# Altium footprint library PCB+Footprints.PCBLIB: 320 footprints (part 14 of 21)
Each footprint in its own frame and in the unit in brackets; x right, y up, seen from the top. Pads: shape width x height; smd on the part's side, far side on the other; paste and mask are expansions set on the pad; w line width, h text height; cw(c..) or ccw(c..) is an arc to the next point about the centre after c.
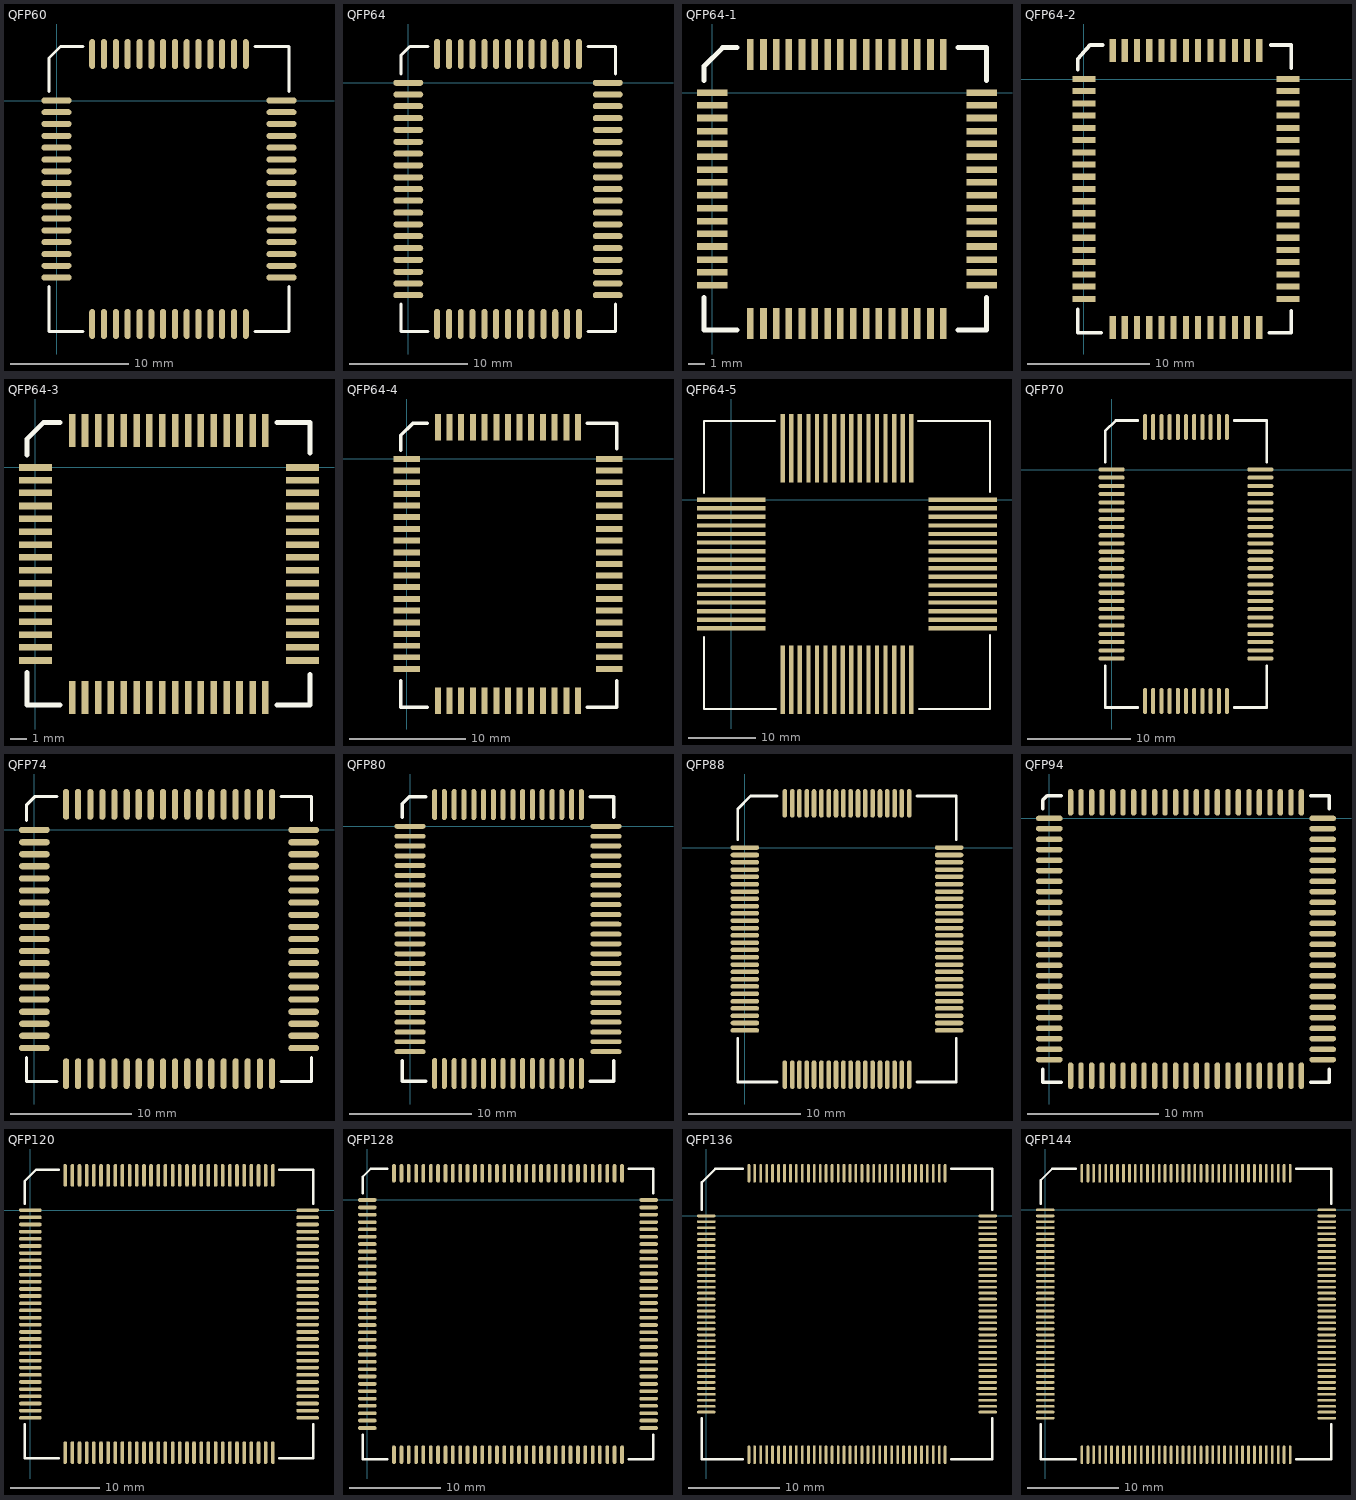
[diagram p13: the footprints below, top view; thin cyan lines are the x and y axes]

## QFP60 [mil]
pads (60):
  oval 100x20 smd: 1(0,0) 2(0,-39) 3(0,-78) 4(0,-118) 5(0,-157) 6(0,-197) 7(0,-236) 8(0,-275) 9(0,-315) 10(0,-354) 11(0,-393) 12(0,-433) 13(0,-472) 14(0,-512) 15(0,-551) 16(0,-590) 31(750,-590) 32(750,-551) 33(750,-512) 34(750,-472) 35(750,-433) 36(750,-393) 37(750,-354) 38(750,-315) 39(750,-275) 40(750,-236) 41(750,-197) 42(750,-157) 43(750,-118) 44(750,-78) 45(750,-39) 46(750,0)
  oval 20x100 smd: 17(119,-745) 18(158,-745) 19(198,-745) 20(237,-745) 21(277,-745) 22(316,-745) 23(355,-745) 24(395,-745) 25(434,-745) 26(473,-745) 27(513,-745) 28(552,-745) 29(592,-745) 30(631,-745) 47(631,155) 48(592,155) 49(552,155) 50(513,155) 51(473,155) 52(434,155) 53(395,155) 54(355,155) 55(316,155) 56(277,155) 57(237,155) 58(198,155) 59(158,155) 60(119,155)
TopOverlay:
  lines w10: -25,-620 -25,-770 89,-770 ; -25,30 -25,142 13,180 89,180 ; 661,-770 775,-770 775,-620 ; 661,180 775,180 775,30

## QFP64 [mil]
pads (64):
  oval 100x20 smd: 1(0,0) 2(0,-39) 3(0,-78) 4(0,-118) 5(0,-157) 6(0,-197) 7(0,-236) 8(0,-275) 9(0,-315) 10(0,-354) 11(0,-393) 12(0,-433) 13(0,-472) 14(0,-511) 15(0,-551) 16(0,-590) 17(0,-630) 18(0,-669) 19(0,-708) 33(665,-708) 34(665,-669) 35(665,-630) 36(665,-590) 37(665,-551) 38(665,-511) 39(665,-472) 40(665,-433) 41(665,-393) 42(665,-354) 43(665,-315) 44(665,-275) 45(665,-236) 46(665,-197) 47(665,-157) 48(665,-118) 49(665,-78) 50(665,-39) 51(665,0)
  oval 20x100 smd: 20(96,-804) 21(136,-804) 22(175,-804) 23(214,-804) 24(254,-804) 25(293,-804) 26(333,-804) 27(372,-804) 28(411,-804) 29(451,-804) 30(490,-804) 31(529,-804) 32(569,-804) 52(569,96) 53(529,96) 54(490,96) 55(451,96) 56(411,96) 57(372,96) 58(333,96) 59(293,96) 60(254,96) 61(214,96) 62(175,96) 63(136,96) 64(96,96)
TopOverlay:
  lines w10: -25,-738 -25,-829 66,-829 ; -25,30 -25,91 5,121 66,121 ; 599,-829 690,-829 690,-738 ; 599,121 690,121 690,30

## QFP64-1 [mil]
pads (64):
  rect 75x16 smd: 1(0,0) 2(0,-31) 3(0,-62) 4(0,-94) 5(0,-125) 6(0,-157) 7(0,-188) 8(0,-219) 9(0,-251) 10(0,-282) 11(0,-314) 12(0,-345) 13(0,-376) 14(0,-408) 15(0,-439) 16(0,-471) 33(658,-471) 34(658,-439) 35(658,-408) 36(658,-376) 37(658,-345) 38(658,-314) 39(658,-282) 40(658,-251) 41(658,-219) 42(658,-188) 43(658,-157) 44(658,-125) 45(658,-94) 46(658,-62) 47(658,-31) 48(658,0)
  rect 16x75 smd: 17(93,-564) 18(125,-564) 19(156,-564) 20(187,-564) 21(219,-564) 22(250,-564) 23(282,-564) 24(313,-564) 25(344,-564) 26(376,-564) 27(407,-564) 28(439,-564) 29(470,-564) 30(501,-564) 31(533,-564) 32(564,-564) 49(564,93) 50(533,93) 51(501,93) 52(470,93) 53(439,93) 54(407,93) 55(376,93) 56(344,93) 57(313,93) 58(282,93) 59(250,93) 60(219,93) 61(187,93) 62(156,93) 63(125,93) 64(93,93)
TopOverlay:
  lines w12: -20,-500 -20,-580 60,-580 ; -20,30 -20,65 25,110 60,110 ; 600,-580 670,-580 670,-500 ; 600,110 670,110 670,30

## QFP64-2 [mil]
pads (64):
  rect 75x20 smd: 1(0,0) 2(0,-39) 3(0,-79) 4(0,-118) 5(0,-158) 6(0,-197) 7(0,-237) 8(0,-276) 9(0,-316) 10(0,-355) 11(0,-395) 12(0,-434) 13(0,-474) 14(0,-513) 15(0,-553) 16(0,-592) 17(0,-632) 18(0,-671) 19(0,-711) 33(660,-711) 34(660,-671) 35(660,-632) 36(660,-592) 37(660,-553) 38(660,-513) 39(660,-474) 40(660,-434) 41(660,-395) 42(660,-355) 43(660,-316) 44(660,-276) 45(660,-237) 46(660,-197) 47(660,-158) 48(660,-118) 49(660,-79) 50(660,-39) 51(660,0)
  rect 20x75 smd: 20(93,-803) 21(132,-803) 22(172,-803) 23(211,-803) 24(251,-803) 25(290,-803) 26(330,-803) 27(369,-803) 28(409,-803) 29(448,-803) 30(488,-803) 31(527,-803) 32(567,-803) 52(567,92) 53(527,92) 54(488,92) 55(448,92) 56(409,92) 57(369,92) 58(330,92) 59(290,92) 60(251,92) 61(211,92) 62(172,92) 63(132,92) 64(93,92)
TopOverlay:
  lines w12: -20,-745 -20,-820 55,-820 ; -20,30 -20,65 20,110 60,110 ; 600,-820 670,-820 670,-750 ; 605,110 670,110 670,35

## QFP64-3 [mil]
pads (64):
  rect 80x16 smd: 1(0,0) 2(0,-31) 3(0,-62) 4(0,-94) 5(0,-125) 6(0,-157) 7(0,-188) 8(0,-219) 9(0,-251) 10(0,-282) 11(0,-314) 12(0,-345) 13(0,-376) 14(0,-408) 15(0,-439) 16(0,-471) 33(652,-471) 34(652,-439) 35(652,-408) 36(652,-376) 37(652,-345) 38(652,-314) 39(652,-282) 40(652,-251) 41(652,-219) 42(652,-188) 43(652,-157) 44(652,-125) 45(652,-94) 46(652,-62) 47(652,-31) 48(652,0)
  rect 16x80 smd: 17(90,-561) 18(121,-561) 19(153,-561) 20(184,-561) 21(216,-561) 22(247,-561) 23(278,-561) 24(310,-561) 25(341,-561) 26(373,-561) 27(404,-561) 28(435,-561) 29(467,-561) 30(498,-561) 31(530,-561) 32(561,-561) 49(561,90) 50(530,90) 51(498,90) 52(467,90) 53(435,90) 54(404,90) 55(373,90) 56(341,90) 57(310,90) 58(278,90) 59(247,90) 60(216,90) 61(184,90) 62(153,90) 63(121,90) 64(90,90)
TopOverlay:
  lines w12: -20,-500 -20,-580 60,-580 ; -20,30 -20,70 20,110 60,110 ; 590,-580 670,-580 670,-505 ; 590,110 670,110 670,35

## QFP64-4 [mil]
pads (64):
  rect 90x20 smd: 1(0,0) 2(0,-39) 3(0,-79) 4(0,-118) 5(0,-158) 6(0,-197) 7(0,-237) 8(0,-276) 9(0,-316) 10(0,-355) 11(0,-395) 12(0,-434) 13(0,-474) 14(0,-513) 15(0,-553) 16(0,-592) 17(0,-632) 18(0,-671) 19(0,-711) 33(685,-711) 34(685,-671) 35(685,-632) 36(685,-592) 37(685,-553) 38(685,-513) 39(685,-474) 40(685,-434) 41(685,-395) 42(685,-355) 43(685,-316) 44(685,-276) 45(685,-237) 46(685,-197) 47(685,-158) 48(685,-118) 49(685,-79) 50(685,-39) 51(685,0)
  rect 20x90 smd: 20(105,-818) 21(145,-818) 22(184,-818) 23(224,-818) 24(263,-818) 25(303,-818) 26(342,-818) 27(382,-818) 28(421,-818) 29(461,-818) 30(500,-818) 31(540,-818) 32(579,-818) 52(579,107) 53(540,107) 54(500,107) 55(461,107) 56(421,107) 57(382,107) 58(342,107) 59(303,107) 60(263,107) 61(224,107) 62(184,107) 63(145,107) 64(105,107)
TopOverlay:
  lines w12: -20,-750 -20,-840 70,-840 ; -20,30 -20,80 20,120 70,120 ; 610,-840 710,-840 710,-750 ; 610,120 710,120 710,35

## QFP64-5 [mil]
pads (64):
  rect 400x25 smd: 1(0,0) 2(0,-50) 3(0,-100) 4(0,-150) 5(0,-200) 6(0,-250) 7(0,-300) 8(0,-350) 9(0,-400) 10(0,-450) 11(0,-500) 12(0,-550) 13(0,-600) 14(0,-650) 15(0,-700) 16(0,-750) 33(1350,-750) 34(1350,-700) 35(1350,-650) 36(1350,-600) 37(1350,-550) 38(1350,-500) 39(1350,-450) 40(1350,-400) 41(1350,-350) 42(1350,-300) 43(1350,-250) 44(1350,-200) 45(1350,-150) 46(1350,-100) 47(1350,-50) 48(1350,0)
  rect 25x400 smd: 17(300,-1050) 18(350,-1050) 19(400,-1050) 20(450,-1050) 21(500,-1050) 22(550,-1050) 23(600,-1050) 24(650,-1050) 25(700,-1050) 26(750,-1050) 27(800,-1050) 28(850,-1050) 29(900,-1050) 30(950,-1050) 31(1000,-1050) 32(1050,-1050) 49(1050,300) 50(1000,300) 51(950,300) 52(900,300) 53(850,300) 54(800,300) 55(750,300) 56(700,300) 57(650,300) 58(600,300) 59(550,300) 60(500,300) 61(450,300) 62(400,300) 63(350,300) 64(300,300)
TopOverlay:
  lines w12: -160,-800 -160,-1220 260,-1220 ; -160,40 -160,460 255,460 ; 1090,460 1510,460 1510,45 ; 1095,-1220 1510,-1220 1510,-790

## QFP70 [mil]
pads (70):
  oval 100x16 smd: 1(0,0) 2(0,-31) 3(0,-63) 4(0,-94) 5(0,-126) 6(0,-157) 7(0,-189) 8(0,-220) 9(0,-252) 10(0,-283) 11(0,-315) 12(0,-346) 13(0,-378) 14(0,-409) 15(0,-441) 16(0,-472) 17(0,-504) 18(0,-535) 19(0,-567) 20(0,-598) 21(0,-630) 22(0,-661) 23(0,-693) 24(0,-724) 36(570,-724) 37(570,-693) 38(570,-661) 39(570,-630) 40(570,-598) 41(570,-567) 42(570,-535) 43(570,-504) 44(570,-472) 45(570,-441) 46(570,-409) 47(570,-378) 48(570,-346) 49(570,-315) 50(570,-283) 51(570,-252) 52(570,-220) 53(570,-189) 54(570,-157) 55(570,-126) 56(570,-94) 57(570,-63) 58(570,-31) 59(570,0)
  oval 16x100 smd: 25(128,-887) 26(159,-887) 27(191,-887) 28(222,-887) 29(254,-887) 30(285,-887) 31(316,-887) 32(348,-887) 33(379,-887) 34(411,-887) 35(442,-887) 60(442,163) 61(411,163) 62(379,163) 63(348,163) 64(316,163) 65(285,163) 66(254,163) 67(222,163) 68(191,163) 69(159,163) 70(128,163)
TopOverlay:
  lines w10: -25,-752 -25,-912 100,-912 ; -25,28 -25,147 16,188 100,188 ; 470,-912 595,-912 595,-752 ; 470,188 595,188 595,28

## QFP74 [mil]
pads (74):
  oval 100x20 smd: 1(0,0) 2(0,-40) 3(0,-79) 4(0,-118) 5(0,-158) 6(0,-197) 7(0,-236) 8(0,-276) 9(0,-315) 10(0,-355) 11(0,-394) 12(0,-433) 13(0,-473) 14(0,-512) 15(0,-551) 16(0,-591) 17(0,-630) 18(0,-669) 19(0,-709) 38(875,-709) 39(875,-669) 40(875,-630) 41(875,-591) 42(875,-551) 43(875,-512) 44(875,-473) 45(875,-433) 46(875,-394) 47(875,-355) 48(875,-315) 49(875,-276) 50(875,-236) 51(875,-197) 52(875,-158) 53(875,-118) 54(875,-79) 55(875,-40) 56(875,0)
  oval 20x100 smd: 20(103,-792) 21(142,-792) 22(182,-792) 23(221,-792) 24(260,-792) 25(300,-792) 26(339,-792) 27(378,-792) 28(418,-792) 29(457,-792) 30(497,-792) 31(536,-792) 32(575,-792) 33(615,-792) 34(654,-792) 35(693,-792) 36(733,-792) 37(772,-792) 57(772,83) 58(733,83) 59(693,83) 60(654,83) 61(615,83) 62(575,83) 63(536,83) 64(497,83) 65(457,83) 66(418,83) 67(378,83) 68(339,83) 69(300,83) 70(260,83) 71(221,83) 72(182,83) 73(142,83) 74(103,83)
TopOverlay:
  lines w10: -25,-739 -25,-817 73,-817 ; -25,30 -25,82 1,108 73,108 ; 802,-817 900,-817 900,-739 ; 802,108 900,108 900,30

## QFP80 [mil]
pads (80):
  oval 100x16 smd: 1(0,0) 2(0,-32) 3(0,-63) 4(0,-95) 5(0,-126) 6(0,-158) 7(0,-189) 8(0,-221) 9(0,-252) 10(0,-284) 11(0,-315) 12(0,-347) 13(0,-378) 14(0,-410) 15(0,-441) 16(0,-473) 17(0,-504) 18(0,-536) 19(0,-567) 20(0,-599) 21(0,-630) 22(0,-662) 23(0,-693) 24(0,-725) 41(630,-725) 42(630,-693) 43(630,-662) 44(630,-630) 45(630,-599) 46(630,-567) 47(630,-536) 48(630,-504) 49(630,-473) 50(630,-441) 51(630,-410) 52(630,-378) 53(630,-347) 54(630,-315) 55(630,-284) 56(630,-252) 57(630,-221) 58(630,-189) 59(630,-158) 60(630,-126) 61(630,-95) 62(630,-63) 63(630,-32) 64(630,0)
  oval 16x100 smd: 25(79,-795) 26(110,-795) 27(142,-795) 28(173,-795) 29(205,-795) 30(236,-795) 31(268,-795) 32(299,-795) 33(331,-795) 34(362,-795) 35(394,-795) 36(425,-795) 37(457,-795) 38(488,-795) 39(520,-795) 40(551,-795) 65(551,70) 66(520,70) 67(488,70) 68(457,70) 69(425,70) 70(394,70) 71(362,70) 72(331,70) 73(299,70) 74(268,70) 75(236,70) 76(205,70) 77(173,70) 78(142,70) 79(110,70) 80(79,70)
TopOverlay:
  lines w10: -25,-753 -25,-820 51,-820 ; -25,28 -25,73 -3,95 51,95 ; 579,-820 655,-820 655,-753 ; 579,95 655,95 655,28

## QFP88 [mil]
pads (88):
  oval 100x16 smd: 1(0,0) 2(0,-26) 3(0,-51) 4(0,-77) 5(0,-102) 6(0,-128) 7(0,-154) 8(0,-179) 9(0,-205) 10(0,-230) 11(0,-256) 12(0,-282) 13(0,-307) 14(0,-333) 15(0,-358) 16(0,-384) 17(0,-410) 18(0,-435) 19(0,-461) 20(0,-486) 21(0,-512) 22(0,-538) 23(0,-563) 24(0,-589) 25(0,-614) 26(0,-640) 45(715,-640) 46(715,-614) 47(715,-589) 48(715,-563) 49(715,-538) 50(715,-512) 51(715,-486) 52(715,-461) 53(715,-435) 54(715,-410) 55(715,-384) 56(715,-358) 57(715,-333) 58(715,-307) 59(715,-282) 60(715,-256) 61(715,-230) 62(715,-205) 63(715,-179) 64(715,-154) 65(715,-128) 66(715,-102) 67(715,-77) 68(715,-51) 69(715,-26) 70(715,0)
  oval 16x100 smd: 27(140,-795) 28(166,-795) 29(191,-795) 30(217,-795) 31(242,-795) 32(268,-795) 33(294,-795) 34(319,-795) 35(345,-795) 36(370,-795) 37(396,-795) 38(421,-795) 39(447,-795) 40(473,-795) 41(498,-795) 42(524,-795) 43(549,-795) 44(575,-795) 71(575,155) 72(549,155) 73(524,155) 74(498,155) 75(473,155) 76(447,155) 77(421,155) 78(396,155) 79(370,155) 80(345,155) 81(319,155) 82(294,155) 83(268,155) 84(242,155) 85(217,155) 86(191,155) 87(166,155) 88(140,155)
TopOverlay:
  lines w10: -25,-668 -25,-820 112,-820 ; -25,28 -25,135 20,180 112,180 ; 603,-820 740,-820 740,-668 ; 603,180 740,180 740,28

## QFP94 [mil]
pads (94):
  oval 80x16 smd: 1(0,0) 2(0,-31) 3(0,-63) 4(0,-94) 5(0,-126) 6(0,-157) 7(0,-189) 8(0,-220) 9(0,-252) 10(0,-283) 11(0,-315) 12(0,-346) 13(0,-378) 14(0,-409) 15(0,-441) 16(0,-472) 17(0,-504) 18(0,-535) 19(0,-567) 20(0,-598) 21(0,-630) 22(0,-661) 23(0,-693) 24(0,-724) 48(820,-724) 49(820,-693) 50(820,-661) 51(820,-630) 52(820,-598) 53(820,-567) 54(820,-535) 55(820,-504) 56(820,-472) 57(820,-441) 58(820,-409) 59(820,-378) 60(820,-346) 61(820,-315) 62(820,-283) 63(820,-252) 64(820,-220) 65(820,-189) 66(820,-157) 67(820,-126) 68(820,-94) 69(820,-63) 70(820,-31) 71(820,0)
  oval 16x80 smd: 25(64,-772) 26(95,-772) 27(127,-772) 28(158,-772) 29(190,-772) 30(221,-772) 31(253,-772) 32(284,-772) 33(316,-772) 34(347,-772) 35(379,-772) 36(410,-772) 37(441,-772) 38(473,-772) 39(504,-772) 40(536,-772) 41(567,-772) 42(599,-772) 43(630,-772) 44(662,-772) 45(693,-772) 46(725,-772) 47(756,-772) 72(756,48) 73(725,48) 74(693,48) 75(662,48) 76(630,48) 77(599,48) 78(567,48) 79(536,48) 80(504,48) 81(473,48) 82(441,48) 83(410,48) 84(379,48) 85(347,48) 86(316,48) 87(284,48) 88(253,48) 89(221,48) 90(190,48) 91(158,48) 92(127,48) 93(95,48) 94(64,48)
TopOverlay:
  lines w10: -20,-752 -20,-792 36,-792 ; -20,28 -20,55 -7,68 36,68 ; 784,-792 840,-792 840,-752 ; 784,68 840,68 840,28

## QFP120 [mil]
pads (120):
  oval 100x16 smd: 1(0,0) 2(0,-32) 3(0,-63) 4(0,-95) 5(0,-126) 6(0,-158) 7(0,-189) 8(0,-221) 9(0,-252) 10(0,-284) 11(0,-315) 12(0,-347) 13(0,-378) 14(0,-410) 15(0,-441) 16(0,-473) 17(0,-504) 18(0,-536) 19(0,-567) 20(0,-599) 21(0,-630) 22(0,-662) 23(0,-693) 24(0,-725) 25(0,-756) 26(0,-788) 27(0,-819) 28(0,-851) 29(0,-882) 30(0,-914) 61(1220,-914) 62(1220,-882) 63(1220,-851) 64(1220,-819) 65(1220,-788) 66(1220,-756) 67(1220,-725) 68(1220,-693) 69(1220,-662) 70(1220,-630) 71(1220,-599) 72(1220,-567) 73(1220,-536) 74(1220,-504) 75(1220,-473) 76(1220,-441) 77(1220,-410) 78(1220,-378) 79(1220,-347) 80(1220,-315) 81(1220,-284) 82(1220,-252) 83(1220,-221) 84(1220,-189) 85(1220,-158) 86(1220,-126) 87(1220,-95) 88(1220,-63) 89(1220,-32) 90(1220,0)
  oval 16x100 smd: 31(153,-1067) 32(185,-1067) 33(216,-1067) 34(248,-1067) 35(279,-1067) 36(311,-1067) 37(342,-1067) 38(374,-1067) 39(405,-1067) 40(437,-1067) 41(468,-1067) 42(500,-1067) 43(531,-1067) 44(563,-1067) 45(594,-1067) 46(626,-1067) 47(657,-1067) 48(689,-1067) 49(720,-1067) 50(752,-1067) 51(783,-1067) 52(815,-1067) 53(846,-1067) 54(878,-1067) 55(909,-1067) 56(941,-1067) 57(972,-1067) 58(1004,-1067) 59(1035,-1067) 60(1067,-1067) 91(1067,153) 92(1035,153) 93(1004,153) 94(972,153) 95(941,153) 96(909,153) 97(878,153) 98(846,153) 99(815,153) 100(783,153) 101(752,153) 102(720,153) 103(689,153) 104(657,153) 105(626,153) 106(594,153) 107(563,153) 108(531,153) 109(500,153) 110(468,153) 111(437,153) 112(405,153) 113(374,153) 114(342,153) 115(311,153) 116(279,153) 117(248,153) 118(216,153) 119(185,153) 120(153,153)
TopOverlay:
  lines w10: -25,-942 -25,-1092 125,-1092 ; -25,28 -25,128 25,178 125,178 ; 1095,-1092 1245,-1092 1245,-942 ; 1095,178 1245,178 1245,28

## QFP128 [mil]
pads (128):
  oval 80x16 smd: 1(0,0) 2(0,-32) 3(0,-63) 4(0,-95) 5(0,-126) 6(0,-158) 7(0,-189) 8(0,-221) 9(0,-252) 10(0,-284) 11(0,-315) 12(0,-347) 13(0,-378) 14(0,-410) 15(0,-441) 16(0,-473) 17(0,-504) 18(0,-536) 19(0,-567) 20(0,-599) 21(0,-630) 22(0,-662) 23(0,-693) 24(0,-725) 25(0,-756) 26(0,-788) 27(0,-819) 28(0,-851) 29(0,-882) 30(0,-914) 31(0,-945) 32(0,-977) 65(1205,-977) 66(1205,-945) 67(1205,-914) 68(1205,-882) 69(1205,-851) 70(1205,-819) 71(1205,-788) 72(1205,-756) 73(1205,-725) 74(1205,-693) 75(1205,-662) 76(1205,-630) 77(1205,-599) 78(1205,-567) 79(1205,-536) 80(1205,-504) 81(1205,-473) 82(1205,-441) 83(1205,-410) 84(1205,-378) 85(1205,-347) 86(1205,-315) 87(1205,-284) 88(1205,-252) 89(1205,-221) 90(1205,-189) 91(1205,-158) 92(1205,-126) 93(1205,-95) 94(1205,-63) 95(1205,-32) 96(1205,0)
  oval 16x80 smd: 33(114,-1091) 34(146,-1091) 35(177,-1091) 36(209,-1091) 37(240,-1091) 38(272,-1091) 39(303,-1091) 40(335,-1091) 41(366,-1091) 42(398,-1091) 43(429,-1091) 44(461,-1091) 45(492,-1091) 46(524,-1091) 47(555,-1091) 48(587,-1091) 49(618,-1091) 50(650,-1091) 51(681,-1091) 52(713,-1091) 53(744,-1091) 54(776,-1091) 55(807,-1091) 56(839,-1091) 57(870,-1091) 58(902,-1091) 59(933,-1091) 60(965,-1091) 61(996,-1091) 62(1028,-1091) 63(1059,-1091) 64(1091,-1091) 97(1091,114) 98(1059,114) 99(1028,114) 100(996,114) 101(965,114) 102(933,114) 103(902,114) 104(870,114) 105(839,114) 106(807,114) 107(776,114) 108(744,114) 109(713,114) 110(681,114) 111(650,114) 112(618,114) 113(587,114) 114(555,114) 115(524,114) 116(492,114) 117(461,114) 118(429,114) 119(398,114) 120(366,114) 121(335,114) 122(303,114) 123(272,114) 124(240,114) 125(209,114) 126(177,114) 127(146,114) 128(114,114)
TopOverlay:
  lines w10: -20,-1005 -20,-1111 86,-1111 ; -20,28 -20,99 15,134 86,134 ; 1119,-1111 1225,-1111 1225,-1005 ; 1119,134 1225,134 1225,28

## QFP136 [mil]
pads (136):
  oval 80x12 smd: 1(0,0) 2(0,-25) 3(0,-51) 4(0,-77) 5(0,-102) 6(0,-128) 7(0,-153) 8(0,-179) 9(0,-204) 10(0,-230) 11(0,-256) 12(0,-281) 13(0,-307) 14(0,-332) 15(0,-358) 16(0,-384) 17(0,-409) 18(0,-435) 19(0,-460) 20(0,-486) 21(0,-512) 22(0,-537) 23(0,-563) 24(0,-588) 25(0,-614) 26(0,-640) 27(0,-665) 28(0,-691) 29(0,-716) 30(0,-742) 31(0,-767) 32(0,-793) 33(0,-819) 34(0,-844) 69(1210,-844) 70(1210,-819) 71(1210,-793) 72(1210,-767) 73(1210,-742) 74(1210,-716) 75(1210,-691) 76(1210,-665) 77(1210,-640) 78(1210,-614) 79(1210,-588) 80(1210,-563) 81(1210,-537) 82(1210,-512) 83(1210,-486) 84(1210,-460) 85(1210,-435) 86(1210,-409) 87(1210,-384) 88(1210,-358) 89(1210,-332) 90(1210,-307) 91(1210,-281) 92(1210,-256) 93(1210,-230) 94(1210,-204) 95(1210,-179) 96(1210,-153) 97(1210,-128) 98(1210,-102) 99(1210,-77) 100(1210,-51) 101(1210,-25) 102(1210,0)
  oval 12x80 smd: 35(183,-1027) 36(208,-1027) 37(234,-1027) 38(260,-1027) 39(285,-1027) 40(311,-1027) 41(336,-1027) 42(362,-1027) 43(387,-1027) 44(413,-1027) 45(439,-1027) 46(464,-1027) 47(490,-1027) 48(515,-1027) 49(541,-1027) 50(567,-1027) 51(592,-1027) 52(618,-1027) 53(643,-1027) 54(669,-1027) 55(695,-1027) 56(720,-1027) 57(746,-1027) 58(771,-1027) 59(797,-1027) 60(823,-1027) 61(848,-1027) 62(874,-1027) 63(899,-1027) 64(925,-1027) 65(950,-1027) 66(976,-1027) 67(1002,-1027) 68(1027,-1027) 103(1027,183) 104(1002,183) 105(976,183) 106(950,183) 107(925,183) 108(899,183) 109(874,183) 110(848,183) 111(823,183) 112(797,183) 113(771,183) 114(746,183) 115(720,183) 116(695,183) 117(669,183) 118(643,183) 119(618,183) 120(592,183) 121(567,183) 122(541,183) 123(515,183) 124(490,183) 125(464,183) 126(439,183) 127(413,183) 128(387,183) 129(362,183) 130(336,183) 131(311,183) 132(285,183) 133(260,183) 134(234,183) 135(208,183) 136(183,183)
TopOverlay:
  lines w10: -20,-870 -20,-1047 157,-1047 ; -20,26 -20,144 39,203 157,203 ; 1053,-1047 1230,-1047 1230,-870 ; 1053,203 1230,203 1230,26

## QFP144 [mil]
pads (144):
  oval 80x12 smd: 1(0,0) 2(0,-26) 3(0,-51) 4(0,-77) 5(0,-103) 6(0,-128) 7(0,-154) 8(0,-179) 9(0,-205) 10(0,-230) 11(0,-256) 12(0,-282) 13(0,-307) 14(0,-333) 15(0,-358) 16(0,-384) 17(0,-410) 18(0,-435) 19(0,-461) 20(0,-486) 21(0,-512) 22(0,-538) 23(0,-563) 24(0,-589) 25(0,-614) 26(0,-640) 27(0,-666) 28(0,-691) 29(0,-717) 30(0,-742) 31(0,-768) 32(0,-793) 33(0,-819) 34(0,-845) 35(0,-870) 36(0,-896) 73(1210,-896) 74(1210,-870) 75(1210,-845) 76(1210,-819) 77(1210,-793) 78(1210,-768) 79(1210,-742) 80(1210,-717) 81(1210,-691) 82(1210,-666) 83(1210,-640) 84(1210,-614) 85(1210,-589) 86(1210,-563) 87(1210,-538) 88(1210,-512) 89(1210,-486) 90(1210,-461) 91(1210,-435) 92(1210,-410) 93(1210,-384) 94(1210,-358) 95(1210,-333) 96(1210,-307) 97(1210,-282) 98(1210,-256) 99(1210,-230) 100(1210,-205) 101(1210,-179) 102(1210,-154) 103(1210,-128) 104(1210,-103) 105(1210,-77) 106(1210,-51) 107(1210,-26) 108(1210,0)
  oval 12x80 smd: 37(157,-1053) 38(183,-1053) 39(208,-1053) 40(234,-1053) 41(260,-1053) 42(285,-1053) 43(311,-1053) 44(336,-1053) 45(362,-1053) 46(387,-1053) 47(413,-1053) 48(439,-1053) 49(464,-1053) 50(490,-1053) 51(515,-1053) 52(541,-1053) 53(567,-1053) 54(592,-1053) 55(618,-1053) 56(643,-1053) 57(669,-1053) 58(695,-1053) 59(720,-1053) 60(746,-1053) 61(771,-1053) 62(797,-1053) 63(823,-1053) 64(848,-1053) 65(874,-1053) 66(899,-1053) 67(925,-1053) 68(950,-1053) 69(976,-1053) 70(1002,-1053) 71(1027,-1053) 72(1053,-1053) 109(1053,157) 110(1027,157) 111(1002,157) 112(976,157) 113(950,157) 114(925,157) 115(899,157) 116(874,157) 117(848,157) 118(823,157) 119(797,157) 120(771,157) 121(746,157) 122(720,157) 123(695,157) 124(669,157) 125(643,157) 126(618,157) 127(592,157) 128(567,157) 129(541,157) 130(515,157) 131(490,157) 132(464,157) 133(439,157) 134(413,157) 135(387,157) 136(362,157) 137(336,157) 138(311,157) 139(285,157) 140(260,157) 141(234,157) 142(208,157) 143(183,157) 144(157,157)
TopOverlay:
  lines w10: -20,-922 -20,-1073 131,-1073 ; -20,26 -20,127 30,177 131,177 ; 1079,-1073 1230,-1073 1230,-922 ; 1079,177 1230,177 1230,26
